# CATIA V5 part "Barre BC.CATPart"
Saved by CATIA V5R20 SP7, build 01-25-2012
Part number: Barre BC
Bounding box of the stored display mesh (mm): x -10 to 10, y 6.857 to 78.857, z 15.856 to 25.311
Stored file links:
  U:\IAO_bon\Barre BC.CATPart
  U:\IAO_bon\Cqueguiner_IAo.CATProduct
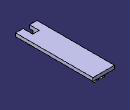
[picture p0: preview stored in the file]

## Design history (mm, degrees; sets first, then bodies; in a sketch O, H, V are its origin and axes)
Set1
  Point1 "Point B/G": linked copy from another document
  Point2 "Point C": linked copy from another document
Body1 (main body)
  Sketch1 on yz-plane, origin (0, 0, 0), H (0, 1, 0), V (0, 0, 1)
    line L1 (78.857, 25.3109) -> (6.857, 25.3109)
    line L2 (6.857, 25.3109) -> (6.857, 22.3109)
    line L3 (6.857, 22.3109) -> (9.857, 22.3109)
    line L4 (15.857, 22.3109) -> (69.857, 22.3109)
    point P7 (75.857, 22.3109)
    line L5 (75.857, 22.3109) -> (78.857, 22.3109)
    line L6 (78.857, 22.3109) -> (78.857, 25.3109)
    line L7 (69.857, 22.3109) -> (69.857, 18.8109)
    arc A1 centre (72.857, 18.8109) radius 3 from (69.857, 18.8109) to (75.857, 18.8109) ccw
    point P10 (72.857, 18.8109)
    line L8 (75.857, 18.8109) -> (75.857, 22.3109)
    line L9 (9.857, 22.3109) -> (9.857, 18.8109)
    arc A2 centre (12.857, 18.8109) radius 3 from (9.857, 18.8109) to (15.857, 18.8109) ccw
    point P13 (12.857, 18.8109)
    line L10 (15.857, 18.8109) -> (15.857, 22.3109)
    reference projected point E1 (12.857, 18.8109) from Point1
    reference projected point E2 (72.857, 18.8109) from Point2
    circle A3 centre (72.857, 18.8109) radius 1.5
    circle A4 centre (12.857, 18.8109) radius 1.5
    distance L5 L4 = 0
    distance L9 L10 = 6
    distance L7 L8 = 6
    distance L5 L1 = 3
    radius A3 = 1.5
    radius A4 = 1.5
    length L9 = 3.5
    horizontal: L1 H, L3 H, L4 H, L5 H
    vertical: L2 V, L6 V, L7 V, L9 V
    coincidence: P7 L3, P13 E1, P10 E2
    tangency: A1 L7, L8 A1, A2 L9, L10 A2
  Pad1: profile Sketch1, direction (1, 0, 0), length 10, opposite side length 10
  Sketch2 on face of Pad1 from Sketch1.L1, origin (0, 0, 25.3109), H (1, 0, 0), V (0, 1, 0)
    line L1 (-3, 15.857) -> (3, 15.857)
    line L2 (3, 15.857) -> (3, -6)
    line L3 (3, -6) -> (-3, -6)
    line L4 (-3, -6) -> (-3, 15.857)
    reference projected line E1 (-10, 6.857) -> (10, 6.857) from edge [face of Pad1 from Sketch1.L2 | face of Pad1 from Sketch1.L1]
    length L1 = 6
    distance L4 V = 3
    distance L1 E1 = 9
    horizontal: L1 H, L3 H
    vertical: L2 V, L4 V
  Pocket1: profile Sketch2, direction (0, 0, -1), length 10
  Sketch3 on face of Pad1 from Sketch1.L4, origin (0, 0, 22.3109), H (1, 0, 0), V (0, -1, 0)
    line L1 (4, -4) -> (21, -4)
    line L2 (21, -4) -> (21, -82)
    line L3 (21, -82) -> (4, -82)
    line L4 (4, -82) -> (4, -4)
    point P5 (-22, -4)
    line L5 (-22, -4) -> (-4, -4)
    line L6 (-4, -4) -> (-4, -82)
    line L7 (-4, -82) -> (-22, -82)
    line L8 (-22, -82) -> (-22, -4)
    point P7 (-4, -82)
    line L9 (-2, -68) -> (2, -68)
    line L10 (2, -68) -> (2, -78)
    line L11 (2, -78) -> (-2, -78)
    line L12 (-2, -78) -> (-2, -68)
    distance L6 V = 4
    distance L4 V = 4
    distance L12 V = 2
    length L9 = 4
    horizontal: L1 H, L3 H, L5 H, L7 H, L9 H, L11 H
    vertical: L2 V, L4 V, L6 V, L8 V, L10 V, L12 V
    coincidence: P5 L1, P7 L3
  Pocket2: profile Sketch3, direction (0, 0, 1), length -10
